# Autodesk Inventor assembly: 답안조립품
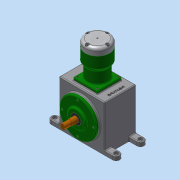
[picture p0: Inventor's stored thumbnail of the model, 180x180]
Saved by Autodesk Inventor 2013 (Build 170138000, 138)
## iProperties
Created: 2016-11
Part Number: 답안조립품
Document SubType Name: Assembly
Designer: Administrator
Mass: 5630.15 g
Surface Area: 4291.84 cm^2
Volume: 1587.81 cm^3
Density: 3.54585 g/cm^3
Author: Administrator
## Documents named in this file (16)
- C:\Users\Administrator\Desktop\361108V1014\답안조립품.iam
- C:\Users\Administrator\Desktop\361108V1014\본체.ipt
- C:\Users\Administrator\Desktop\361108V1014\베어링 20 x 47 x 14.ipt
- C:\Users\Administrator\Desktop\361108V1014\메인크랭크축.ipt
- C:\Users\Administrator\Desktop\361108V1014\베어링 NA 4902.ipt
- C:\Users\Administrator\Desktop\361108V1014\크랭크보조축.ipt
- C:\Users\Administrator\Desktop\361108V1014\앞커버.ipt
- C:\Users\Administrator\Desktop\361108V1014\오일 실 20 35 8.ipt
- C:\Users\Administrator\Desktop\361108V1014\실린더.ipt
- C:\Users\Administrator\Desktop\361108V1014\피스톤.ipt
- C:\Users\Administrator\Desktop\361108V1014\커넥팅로드.ipt
- C:\Users\Administrator\Desktop\361108V1014\피스톤핀.ipt
- C:\Users\Administrator\Desktop\361108V1014\실린더헤드.ipt
- C:\Users\Administrator\Desktop\361108V1014\가변스프링.ipt
- C:\Users\Administrator\Desktop\361108V1014\볼트 M4 x 8.ipt
- C:\Users\Administrator\Desktop\361108V1014\볼트 M5 x 20.ipt
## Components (15 placed, 5 different names)
1. 피스톤:1
2. 피스톤핀:1
3. 가변스프링:1
4. ISO 4762 M4 x 8:2
5. ISO 4762 M4 x 8:6
6. ISO 4762 M4 x 8:7
7. ISO 4762 M4 x 8:8
8. ISO 4762 M4 x 8:1
9. ISO 4762 M4 x 8:3
10. ISO 4762 M4 x 8:4
11. ISO 4762 M4 x 8:5
12. ISO 4762 M5 x 20:1
13. ISO 4762 M5 x 20:2
14. ISO 4762 M5 x 20:3
15. ISO 4762 M5 x 20:4
